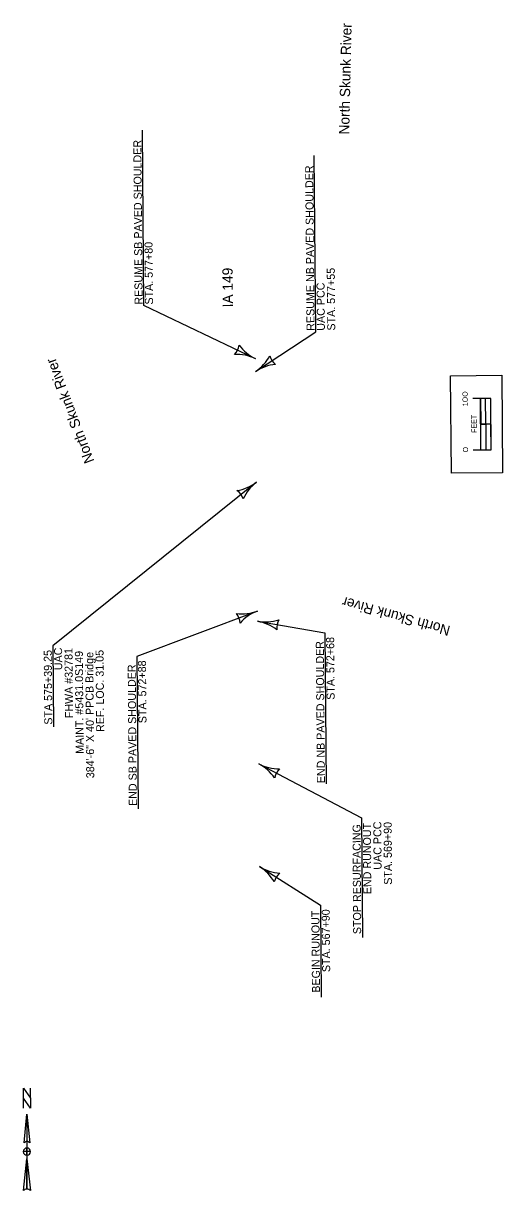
# Model space of a CAD drawing. Extents: x 23417754 to 23421386, y 6737896 to 6790956.
# Drawn here: x 23420409 to 23421343, y 6781728 to 6784004 of the extents above; entities that cross this region are included whole.
import ezdxf

# ---------------------------------------------------------------- set-up
doc = ezdxf.new("R2010")
doc.units = 0
for name, color, linetype in [('Curb', 7, 'Continuous'), ('Default', 7, 'Continuous'), ('dsnCellElements', 7, 'Continuous'), ('RasterAttachment', 7, 'Continuous'), ('TextAlignmentLrg', 7, 'Continuous')]:
    doc.layers.add(name, color=color, linetype=linetype)

msp = doc.modelspace()

# ---------------------------------------------------------------- linework, layer by layer
at = {"layer": 'Curb'}
msp.add_line((23421319.9, 6783222.7), (23421299.9, 6783222.5), dxfattribs=at)
msp.add_line((23421319.9, 6783222.7), (23421299.9, 6783222.5), dxfattribs=at)
for points in [[(23421242.7, 6783127), (23421241.1, 6783317), (23421341.1, 6783317.8), (23421342.7, 6783127.8)], [(23421342.7, 6783127.8), (23421242.7, 6783127), (23421241.1, 6783317), (23421341.1, 6783317.8)], [(23421309.8, 6783222.6), (23421309.4, 6783272.6), (23421299.5, 6783272.5), (23421299.9, 6783222.5)], [(23421320.3, 6783172.7), (23421319.9, 6783222.7), (23421309.8, 6783222.6), (23421310.2, 6783172.6)]]:
    msp.add_lwpolyline(points, close=True, dxfattribs=at)
for points in [[(23421285.3, 6783172.4), (23421320.3, 6783172.7), (23421319.5, 6783272.7), (23421284.5, 6783272.4)], [(23421300.3, 6783172.5), (23421299.5, 6783272.5)]]:
    msp.add_lwpolyline(points, dxfattribs=at)
at = {"layer": 'dsnCellElements'}
for points in [[(23420860.8, 6783350.1), (23420643.6, 6783453.7), (23420640.8, 6783795.9)], [(23420861, 6783325.1), (23420978.3, 6783402.8), (23420975.4, 6783746.5)], [(23420862.8, 6783109.4), (23420466, 6782790.6), (23420467.3, 6782632.1)], [(23420864.9, 6782858.2), (23420629.8, 6782769.8), (23420632.3, 6782472.4)], [(23420865, 6782838.2), (23420996.2, 6782815.4), (23420998.6, 6782521.3)], [(23420867.5, 6782560.2), (23421067.9, 6782455.2), (23421069.3, 6782222)], [(23420869, 6782360.2), (23420987.5, 6782284.5), (23420989, 6782105.6)]]:
    msp.add_lwpolyline(points, dxfattribs=at)
for centre, radius, start, end in [((23420796.5, 6783380.8), 32.8, 316.7806, 352.2473), ((23420897.4, 6783426.9), 85, 216.4414, 244.5139), ((23420824.2, 6783273.4), 85, 64.5139, 92.5864), ((23420814.1, 6783396), 85, 303.5194, 331.5919), ((23420920.5, 6783364.5), 32.8, 195.7861, 231.2528), ((23420908, 6783254.2), 85, 95.4469, 123.5194), ((23420810.9, 6783176.7), 85, 279.5659, 307.6384), ((23420806.3, 6783065.9), 32.8, 19.905, 55.3717), ((23420914.7, 6783042.1), 85, 127.6384, 155.7109), ((23420835, 6782937.7), 85, 262.5306, 290.603), ((23420798.1, 6782833.1), 32.8, 2.8697, 38.3364), ((23420894.8, 6782778.6), 85, 110.603, 138.6755), ((23420879.6, 6782921.9), 85, 260.1734, 288.2459), ((23420935.3, 6782826), 32.8, 152.4401, 187.9068), ((23420850.5, 6782754.4), 85, 52.1009, 80.1734), ((23420828, 6782484.8), 85, 34.2836, 62.356), ((23420907, 6782635.5), 85, 242.356, 270.4285), ((23420930.7, 6782527.1), 32.8, 134.6227, 170.0894), ((23420823.2, 6782288.5), 85, 29.3532, 57.4257), ((23420914.8, 6782431.8), 85, 237.4257, 265.4982), ((23420929.1, 6782321.8), 32.8, 129.6924, 165.1591)]:
    msp.add_arc(centre, radius, start, end, dxfattribs=at)
at = {"layer": 'TextAlignmentLrg'}
for p, q in [((23420415.6, 6781877.5), (23420421.3, 6781821.2)), ((23420415.6, 6781877.5), (23420415.6, 6781731)), ((23420410, 6781821.2), (23420410, 6781821.2)), ((23420410.2, 6781821.7), (23420411.3, 6781822.9)), ((23420415.6, 6781797.2), (23420415.6, 6781797.2)), ((23420408.6, 6781728.2), (23420415.6, 6781790.2))]:
    msp.add_line(p, q, dxfattribs=at)
msp.add_lwpolyline([(23420422.7, 6781888.8), (23420408.6, 6781908.5), (23420408.6, 6781928.2), (23420422.7, 6781908.5)], close=True, dxfattribs=at)
for points in [[(23420408.6, 6781888.8), (23420408.6, 6781928.2), (23420422.7, 6781908.5), (23420422.7, 6781928.2)], [(23420410, 6781821.2), (23420415.6, 6781877.5), (23420415.6, 6781824)], [(23420415.6, 6781797.2), (23420415.6, 6781804.3), (23420408.6, 6781804.3)], [(23420422.7, 6781804.3), (23420415.6, 6781804.3), (23420415.6, 6781811.3)], [(23420415.6, 6781731), (23420415.6, 6781790.2), (23420422.7, 6781728.2)]]:
    msp.add_lwpolyline(points, dxfattribs=at)
for centre, radius, start, end in [((23420415.7, 6781816.9), 7.04, 90.0204, 143.1257), ((23420415.7, 6781816.9), 7.04, 36.8481, 90.0218), ((23420415.6, 6781804.3), 7.04, 90, 180), ((23420415.6, 6781804.3), 7.04, 180, 270), ((23420415.6, 6781804.3), 7.04, 0, 90), ((23420415.6, 6781804.3), 7.04, 270, 360), ((23420415.6, 6781720.8), 10.2, 89.9894, 133.619), ((23420415.6, 6781720.8), 10.2, 46.4021, 90.0006)]:
    msp.add_arc(centre, radius, start, end, dxfattribs=at)

# ---------------------------------------------------------------- texts
at = {"layer": 'Curb'}
for s, p in [('1OO', (23421274.6, 6783257.4)), ('1OO', (23421274.6, 6783257.4)), ('FEET', (23421292, 6783205.5)), ('O', (23421275.3, 6783167.4)), ('O', (23421275.3, 6783167.4))]:
    msp.add_text(s, height=10, rotation=90.4726, dxfattribs=at).set_placement(p)
at = {"layer": 'Default'}
msp.add_text('IA 149', height=20, rotation=90.4726, dxfattribs=at).set_placement((23420817.1, 6783450.2))
at = {"layer": 'dsnCellElements'}
for s, height, rotation, p in [('RESUME SB PAVED SHOULDER', 15.605, 90.4726, (23420641.1, 6783455.5)), ('RESUME NB PAVED SHOULDER', 15.605, 90.4726, (23420976.1, 6783404.6)), ('STA. 577+80', 15.605, 90.4726, (23420661.3, 6783455.6)), ('STA. 577+55', 15.605, 90.4726, (23421016.5, 6783404.9)), ('UAC PCC', 15.6, 90.4726, (23420996.3, 6783404.7)), ('END NB PAVED SHOULDER', 15.605, 90.4726, (23420996.4, 6782522.6)), ('STA. 572+68', 15.605, 90.4726, (23421015.3, 6782685.2)), ('STA 575+39.25', 15.605, 90.4726, (23420465.1, 6782636.7)), ('UAC', 15.6, 90.4726, (23420484.4, 6782742.9)), ('FHWA #32781', 15.605, 90.4726, (23420505.4, 6782649.3)), ('MAINT. #5431.0S149', 15.605, 90.4726, (23420526.2, 6782579.8)), ('384\'-6" X 40\' PPCB Bridge', 15.605, 90.4726, (23420546.8, 6782532.3)), ('REF. LOC. 31.05', 15.605, 90.4726, (23420566.2, 6782622.4)), ('END SB PAVED SHOULDER', 15.605, 90.4726, (23420629.8, 6782478.2)), ('STA. 572+88', 15.605, 90.4726, (23420648.6, 6782639.5)), ('STOP RESURFACING', 15.605, 90.2849, (23421066.9, 6782228.3)), ('END RUNOUT', 15.6, 90.2849, (23421086.7, 6782306.2)), ('UAC PCC', 15.6, 90.2849, (23421106.7, 6782354)), ('STA. 569+90', 15.605, 90.2849, (23421127, 6782324.6)), ('BEGIN RUNOUT', 15.605, 90.4726, (23420986.8, 6782114.2)), ('STA. 567+90', 15.605, 90.4726, (23421006.6, 6782154.3))]:
    msp.add_text(s, height=height, rotation=rotation, dxfattribs=at).set_placement(p)
at = {"layer": 'RasterAttachment'}
for rotation, p in [(88.7347, (23421043.6, 6783787)), (110.6969, (23420547.2, 6783150.6)), (164.4902, (23421242, 6782828.5))]:
    msp.add_text('North Skunk River', height=20, rotation=rotation, dxfattribs=at).set_placement(p)

doc.saveas('drawing.dxf')
